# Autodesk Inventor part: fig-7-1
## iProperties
Created: 2004-05
Part Number: fig-7-1
Document SubType Name: Modeling
Designer: CADCIM Technologies
Manufacturer: Standard
Standards Organization: Custom
Author: CADCIM Technologies
